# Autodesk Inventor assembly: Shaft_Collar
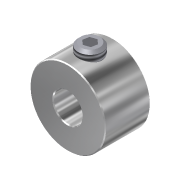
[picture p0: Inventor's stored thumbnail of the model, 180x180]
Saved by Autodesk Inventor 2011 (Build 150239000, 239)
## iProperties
Created: 2008-03
Part Number: Shaft_Collar
Document SubType Name: Assembly
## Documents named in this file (3)
- C:\Data Folder\VEX 2011\Inventor Datasets\Unit 16\Components\Shaft_Collar.iam
- C:\Data Folder\VEX 2011\Inventor Datasets\Unit 16\Components\SHAFT-COLLAR.ipt
- C:\Data Folder\VEX 2011\Inventor Datasets\Unit 16\Content Center\en-US\ANSI B18.3(08)\ANSI B18.3 - 6-40 UNF - 0.188(24).ipt
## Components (2 placed, 2 different names)
1. SHAFT-COLLAR:1 — Mate:2
2. Hexagon Socket Set Screw - Flat Point - Inch 6-40 UNF x 0.188:2 — Mate:2, Flush:2
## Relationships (2: Mate 1, Flush 1)
- Mate:2: SHAFT-COLLAR:1 ↔ Hexagon Socket Set Screw - Flat Point - Inch 6-40 UNF x 0.188:2
- Flush:2: Hexagon Socket Set Screw - Flat Point - Inch 6-40 UNF x 0.188:2
